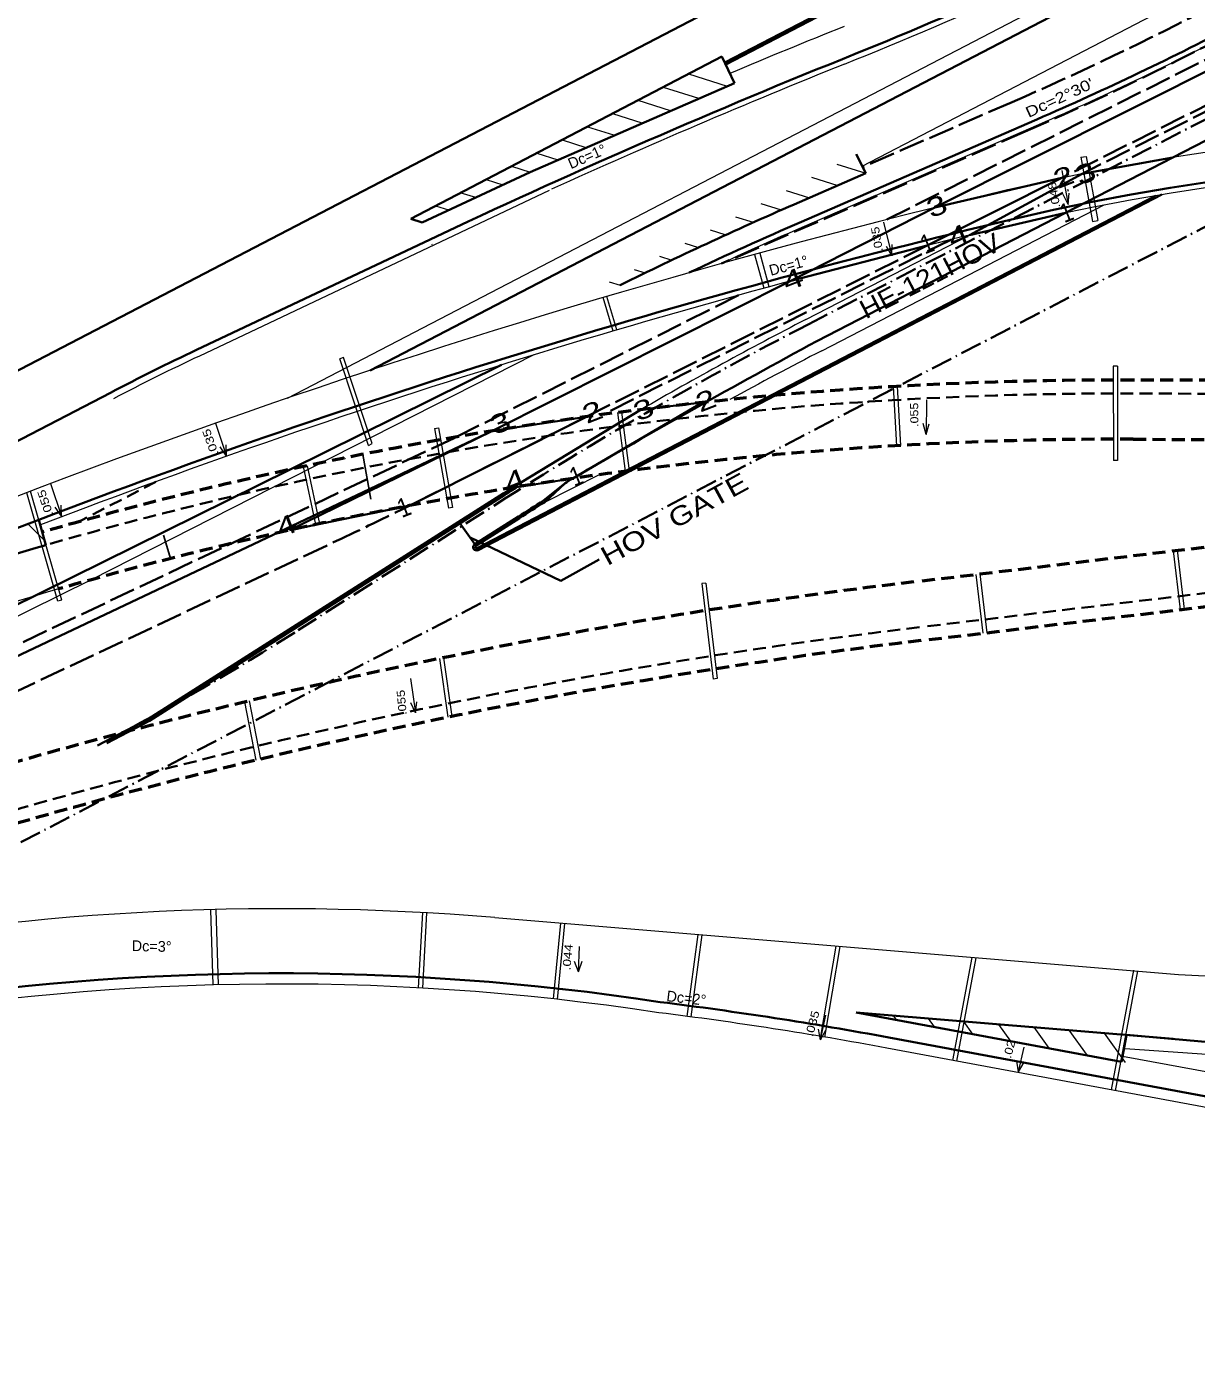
# Model space of a CAD drawing. Extents: x 2354993 to 2372084, y 6966390 to 6990057.
# Drawn here: x 2362136 to 2363006, y 6977334 to 6978319 of the extents above; entities that cross this region are included whole.
import ezdxf
from ezdxf.enums import TextEntityAlignment as Align

# ---------------------------------------------------------------- set-up
doc = ezdxf.new("R2010")
doc.units = 0
doc.header["$LTSCALE"] = 3.2
for name, pattern in [('DOT_DASHED', [7.7, 5, -1.2, 0.3, -1.2]), ('LONG_DASHED', [7.5, 6, -1.5]), ('MEDIUM_DASHED', [4.5, 3, -1.5])]:
    doc.linetypes.add(name, pattern=pattern)
for name, color, linetype, lineweight in [('12', 7, 'Continuous', 13), ('13', 7, 'Continuous', 13), ('17', 7, 'Continuous', 13), ('19', 7, 'Continuous', 13), ('2', 7, 'Continuous', 35), ('4', 7, 'Continuous', 13), ('5', 7, 'Continuous', 35), ('6', 7, 'Continuous', 35), ('61', 7, 'Continuous', 13), ('63', 7, 'Continuous', 35)]:
    doc.layers.add(name, color=color, linetype=linetype, lineweight=lineweight)

msp = doc.modelspace()

# ---------------------------------------------------------------- linework, layer by layer
at = {"layer": '12'}
for p, q in [((2362574.682, 6978093.733), (2362567.324, 6978118.67)), ((2362571.803, 6978092.884), (2362564.446, 6978117.821)), ((2362371.377, 6978073.296), (2362368.532, 6978072.348)), ((2362390.025, 6978007.891), (2362368.532, 6978072.348)), ((2362392.719, 6978009.291), (2362371.377, 6978073.296)), ((2362946.885, 6978066.796), (2362943.878, 6978066.795)), ((2362943.885, 6978066.795), (2362943.935, 6977996.56)), ((2362946.885, 6978066.796), (2362946.934, 6977996.561)), ((2362780.042, 6978051.58), (2362782.606, 6978007.655)), ((2362783.038, 6978051.756), (2362785.602, 6978007.831)), ((2362575.239, 6978032.315), (2362580.866, 6977988.676)), ((2362578.214, 6978032.698), (2362583.841, 6977989.06)), ((2362439.038, 6978020.407), (2362441.991, 6978020.93)), ((2362439.038, 6978020.407), (2362449.499, 6977961.336)), ((2362441.991, 6978020.93), (2362452.451, 6977961.859)), ((2362389.745, 6978018.211), (2362386.9, 6978017.263)), ((2362341.312, 6977992.101), (2362350.49, 6977949.069)), ((2362344.245, 6977992.726), (2362353.424, 6977949.694)), ((2362946.949, 6977996.561), (2362943.935, 6977996.56)), ((2362159.001, 6977891.989), (2362135.767, 6977972.726)), ((2362161.883, 6977892.818), (2362138.577, 6977973.802)), ((2362452.451, 6977961.859), (2362449.499, 6977961.336)), ((2362161.883, 6977892.818), (2362159.001, 6977891.989)), ((2362272.444, 6977662.559), (2362274.102, 6977606.792)), ((2362276.443, 6977662.678), (2362278.1, 6977606.896))]:
    msp.add_line(p, q, dxfattribs=at)
for points in [[(2362640.897, 6977905.496), (2362637.913, 6977905.14), (2362646.394, 6977834.183)], [(2362640.897, 6977905.496), (2362649.372, 6977834.54), (2362646.391, 6977834.183)]]:
    msp.add_lwpolyline(points, dxfattribs=at)
at = {"layer": '17'}
for p, q in [((2362919.834, 6978222.065), (2362923.771, 6978222.772)), ((2362919.834, 6978222.065), (2362928.413, 6978174.288)), ((2362923.771, 6978222.772), (2362932.35, 6978174.995)), ((2362928.413, 6978174.288), (2362932.35, 6978174.995)), ((2362677.146, 6978149.827), (2362683.958, 6978124.875)), ((2362681.005, 6978150.881), (2362687.817, 6978125.928)), ((2362546.028, 6977616.636), (2362546.795, 6977635.37)), ((2362546.028, 6977616.636), (2362543.26, 6977624.219)), ((2362546.028, 6977616.636), (2362548.839, 6977624.427)), ((2362726.084, 6977566.046), (2362730.092, 6977584.363)), ((2362726.084, 6977566.046), (2362724.675, 6977573.994)), ((2362726.084, 6977566.046), (2362730.206, 6977573.23)), ((2362873.476, 6977542.299), (2362877.484, 6977560.616)), ((2362873.476, 6977542.3), (2362872.067, 6977550.248)), ((2362873.476, 6977542.3), (2362877.598, 6977549.484))]:
    msp.add_line(p, q, dxfattribs=at)
at = {"layer": '17', "lineweight": 35}
msp.add_line((2361706.685, 6977651.285), (2362482.125, 6978018.666), dxfattribs=at)
at = {"layer": '19'}
for p, q in [((2362905.52, 6978212.363), (2362910.407, 6978187.048)), ((2362910.407, 6978187.048), (2362906.655, 6978194.465)), ((2362910.407, 6978187.048), (2362911.126, 6978195.322)), ((2362779.224, 6978148.867), (2362775.199, 6978155.884)), ((2362804.585, 6978016.032), (2362802.457, 6978024.066)), ((2362284.473, 6977999.932), (2362279.726, 6978006.753)), ((2362161.719, 6977955.18), (2362156.972, 6977962.001)), ((2362424.912, 6977809.025), (2362421.526, 6977816.614))]:
    msp.add_line(p, q, dxfattribs=at)
for points in [[(2362773.018, 6978173.891), (2362779.224, 6978148.867), (2362779.509, 6978157.168)], [(2362805.067, 6978041.81), (2362804.585, 6978016.032), (2362807.009, 6978023.976)], [(2362276.11, 6978024.32), (2362284.473, 6977999.932), (2362284.034, 6978008.226)], [(2362153.356, 6977979.568), (2362161.719, 6977955.18), (2362161.28, 6977963.474)], [(2362421.264, 6977834.548), (2362424.912, 6977809.025), (2362426.034, 6977817.254)]]:
    msp.add_lwpolyline(points, dxfattribs=at)
at = {"layer": '2'}
for p, q in [((2358006.591, 6975920.846), (2363488.891, 6978770.331)), ((2362811.106, 6978184.667), (2363604.71, 6978582.7)), ((2362988.207, 6978222.005), (2363089.737, 6978274.358)), ((2362759.919, 6978210.266), (2362752.541, 6978224.463)), ((2362975.243, 6978193.546), (2362580.871, 6977988.675)), ((2362980.038, 6978194.347), (2362692.88, 6978045.172)), ((2362723.338, 6978085.426), (2362908.292, 6978180.797)), ((2362704.108, 6978130.197), (2362482.125, 6978018.666)), ((2362692.88, 6978045.172), (2362471.439, 6977930.136)), ((2362580.871, 6977988.675), (2362470.748, 6977931.467)), ((2362226.42, 6977804.541), (2362490.493, 6977972.46)), ((2362227.174, 6977803.242), (2362491.298, 6977971.194)), ((2362468.945, 6977934.464), (2362501.492, 6977955.16)), ((2362469.73, 6977933.185), (2362502.297, 6977953.894)), ((2362457.957, 6977949.993), (2362468.945, 6977934.464)), ((2362532.928, 6977907.156), (2362465.571, 6977939.397)), ((2362532.928, 6977907.156), (2362561.479, 6977922.997))]:
    msp.add_line(p, q, dxfattribs=at)
at = {"layer": '2', "linetype": 'LONG_DASHED'}
for p, q in [((2362775.435, 6978175.726), (2363601.123, 6978589.851)), ((2363618.55, 6978565.019), (2362905.562, 6978206.794)), ((2363084.717, 6978292.33), (2362920.65, 6978209.898)), ((2362868.725, 6978263.158), (2362757.536, 6978214.854)), ((2362878.281, 6978241.142), (2362652.39, 6978143.01)), ((2362822.936, 6978160.805), (2362564.328, 6978030.873)), ((2362805.354, 6978156.448), (2362420.606, 6977963.184)), ((2362665.112, 6978119.556), (2362455.357, 6978014.169)), ((2361699.088, 6977656.554), (2362455.357, 6978014.169)), ((2361711.836, 6977629.398), (2362366.21, 6977936.92))]:
    msp.add_line(p, q, dxfattribs=at)
at = {"layer": '2', "linetype": 'MEDIUM_DASHED'}
msp.add_line((2362231.704, 6977980.832), (2362174.616, 6977951.163), dxfattribs=at)
at = {"layer": '2', "linetype": 'LONG_DASHED'}
for centre, radius, start, end in [((2361957.93, 6980359.697), 2285.831, 293.48147, 297.64944), ((2361957.927, 6980359.696), 2309.831, 293.48137, 297.6495), ((2361144.348, 6980536.913), 2872.789, 295.17109, 296.37586)]:
    msp.add_arc(centre, radius, start, end, dxfattribs=at)
at = {"layer": '2'}
for centre, radius, start, end in [((2365652.69, 6972668.039), 6158.667, 118.40149, 120.33806), ((2364029.86, 6975551.655), 2850.789, 121.46196, 121.59891), ((2364029.86, 6975551.655), 2868.789, 122.30227, 122.45191), ((2364029.86, 6975551.655), 2867.289, 122.23233, 122.45191), ((2364029.86, 6975551.655), 2848.289, 122.00852, 122.45191), ((2364029.86, 6975551.655), 2846.789, 122.01179, 122.45191), ((2362470.287, 6977932.355), 2.5, 122.45143, 297.45154), ((2362470.287, 6977932.355), 1, 122.45143, 297.45154)]:
    msp.add_arc(centre, radius, start, end, dxfattribs=at)
at = {"layer": '4'}
msp.add_line((2362757.154, 6978215.587), (2363268.695, 6978481.438), dxfattribs=at)
at = {"layer": '4', "lineweight": 25}
for p, q in [((2362385.833, 6978001.212), (2362391.796, 6977967.815)), ((2362242.862, 6977923.152), (2362237.538, 6977941.259))]:
    msp.add_line(p, q, dxfattribs=at)
at = {"layer": '4', "lineweight": 35}
for p in [(2362520.138, 6977966.916), (2362520.795, 6977965.558)]:
    msp.add_line(p, (2362536.133, 6977979.777), dxfattribs=at)
at = {"layer": '5'}
for p, q in [((2362087.371, 6978041.876), (2363419.143, 6978734.078)), ((2362654.988, 6978292.473), (2363507.292, 6978735.395)), ((2362655.626, 6978291.114), (2363508.018, 6978734.082)), ((2362391.142, 6978063.692), (2363583.984, 6978683.611)), ((2362652.848, 6978297.032), (2362421.419, 6978176.314)), ((2362652.848, 6978297.032), (2362662.138, 6978277.243)), ((2362742.392, 6978295.091), (2362751.833, 6978298.893)), ((2362765.497, 6978197.425), (2362886.96, 6978250.192)), ((2362759.919, 6978210.266), (2362706.512, 6978187.064)), ((2362765.497, 6978197.425), (2362712.091, 6978174.224)), ((2362421.419, 6978176.314), (2362429.768, 6978173.689)), ((2362435.758, 6978161.035), (2362262.045, 6978078.872)), ((2361730.202, 6977803.996), (2362197.968, 6978047.082)), ((2362144.684, 6977952.584), (2362150.078, 6977933.84)), ((2362226.42, 6977804.541), (2362188.485, 6977784.834)), ((2362227.178, 6977803.244), (2362195.267, 6977786.667)), ((2362752.746, 6977586.338), (2362988.499, 6977566.726)), ((2363437.708, 6977444.706), (2362776.995, 6977567.714)), ((2362949.929, 6977549.759), (2362953.59, 6977569.421)), ((2363056.715, 6977560.454), (2362953.628, 6977569.627))]:
    msp.add_line(p, q, dxfattribs=at)
at = {"layer": '5', "lineweight": 13}
for p, q in [((2362329.78, 6978043.07), (2363248.405, 6978520.479)), ((2362627.951, 6978284.047), (2362656.76, 6978274.985)), ((2362609.144, 6978274.236), (2362635.439, 6978265.969)), ((2362590.336, 6978264.425), (2362614.259, 6978256.904)), ((2362571.528, 6978254.614), (2362593.203, 6978247.8)), ((2362767.091, 6978193.757), (2362888.554, 6978246.524)), ((2362552.719, 6978244.803), (2362572.28, 6978238.654)), ((2362533.911, 6978234.992), (2362551.488, 6978229.467)), ((2362515.102, 6978225.182), (2362530.824, 6978220.239)), ((2362738.3, 6978217.063), (2362759.919, 6978210.266)), ((2362496.294, 6978215.371), (2362510.289, 6978210.971)), ((2362719.45, 6978207.266), (2362738.922, 6978201.144)), ((2362524.395, 6978197.427), (2362264.183, 6978074.352)), ((2362477.487, 6978205.559), (2362489.88, 6978201.664)), ((2362700.597, 6978197.468), (2362717.922, 6978192.021)), ((2362458.678, 6978195.749), (2362469.594, 6978192.317)), ((2362681.747, 6978187.672), (2362696.925, 6978182.899)), ((2362767.091, 6978193.756), (2362713.852, 6978170.627)), ((2362439.869, 6978185.939), (2362449.429, 6978182.933)), ((2362662.895, 6978177.874), (2362675.926, 6978173.777)), ((2362727.004, 6978078.316), (2362937.068, 6978186.635)), ((2362644.044, 6978168.078), (2362654.929, 6978164.655)), ((2362435.377, 6978160.855), (2362435.764, 6978161.038)), ((2362437.088, 6978157.239), (2362437.474, 6978157.422)), ((2362625.192, 6978158.28), (2362635.464, 6978155.051)), ((2362715.089, 6978101.424), (2362836.859, 6978164.214)), ((2362606.34, 6978148.483), (2362615.458, 6978145.615)), ((2362587.489, 6978138.686), (2362595.692, 6978136.108)), ((2362568.958, 6978129.604), (2362577.161, 6978127.026)), ((2362512.875, 6978075.151), (2362183.72, 6977908.026)), ((2362562.03, 6977986.161), (2362520.795, 6977965.558)), ((2362136.625, 6977949.49), (2362149.095, 6977937.256)), ((2362183.72, 6977908.026), (2361804.561, 6977720.528)), ((2362483.973, 6977656.862), (2362992.478, 6977614.561)), ((2362782.547, 6977580.921), (2362780.307, 6977584.045)), ((2362810.95, 6977575.633), (2362806.479, 6977581.868)), ((2362839.354, 6977570.345), (2362832.652, 6977579.691)), ((2362867.758, 6977565.057), (2362858.825, 6977577.513)), ((2362896.161, 6977559.769), (2362884.997, 6977575.336)), ((2362924.565, 6977554.481), (2362911.17, 6977573.159)), ((2362952.969, 6977549.193), (2362937.343, 6977570.982)), ((2363436.244, 6977436.841), (2362775.531, 6977559.85)), ((2362952.814, 6977559.66), (2363056.326, 6977552.462)), ((2363441.003, 6977462.402), (2362950.662, 6977553.691))]:
    msp.add_line(p, q, dxfattribs=at)
at = {"layer": '5', "linetype": 'MEDIUM_DASHED', "lineweight": 53}
for p, q in [((2363881.241, 6978053.379), (2362958.761, 6978056.492)), ((2362958.612, 6978012.492), (2363716.295, 6978009.935)), ((2362801.702, 6977907.216), (2363080.587, 6977940.529)), ((2362806.918, 6977863.526), (2363091.58, 6977897.529))]:
    msp.add_line(p, q, dxfattribs=at)
at = {"layer": '5', "linetype": 'MEDIUM_DASHED'}
for p, q in [((2363836.954, 6978043.529), (2362958.726, 6978046.492)), ((2362805.732, 6977873.455), (2363090.394, 6977907.458))]:
    msp.add_line(p, q, dxfattribs=at)
at = {"layer": '5'}
for points in [[(2362662.138, 6978277.243), (2362510.289, 6978210.971), (2362429.768, 6978173.689)], [(2362488.793, 6978067.704), (2362331.734, 6977990.029), (2361705.614, 6977680.376)], [(2362949.929, 6977549.759), (2362839.354, 6977570.345), (2362752.746, 6977586.338)]]:
    msp.add_lwpolyline(points, dxfattribs=at)
for centre, radius, start, end in [((2361676.37, 6980969.25), 2878.789, 291.93666, 297.46082), ((2361968.189, 6980365.073), 2305.831, 293.48164, 297.64942), ((2364877.625, 6972993.336), 5715.578, 111.93666, 115.2919), ((2363244.672, 6976597.082), 1623.014, 38.12295, 103.3303), ((2363855.57, 6975542.087), 2883.789, 113.48158, 116.31519), ((2364188.171, 6972614.757), 5715.613, 103.3303, 110.94842), ((2363855.57, 6975542.087), 2869.789, 113.48158, 115.31325), ((2363078.527, 6976352.647), 1909.58, 115.31354, 117.45987), ((2364188.16, 6972614.79), 5715.578, 110.94799, 113.39373), ((2362948.983, 6975157.719), 2888.789, 106.05464, 110.92598), ((2362324.651, 6975741.618), 1873.859, 81.33444, 116.95937), ((2362255.214, 6974765.083), 2850.789, 79.45368, 82.91209)]:
    msp.add_arc(centre, radius, start, end, dxfattribs=at)
at = {"layer": '5', "lineweight": 13}
for centre, radius, start, end in [((2361676.37, 6980969.25), 2882.789, 291.73437, 297.46082), ((2364877.625, 6972993.336), 5737.578, 111.83502, 112.75114), ((2361968.189, 6980365.073), 2309.831, 293.48164, 297.64942), ((2364877.625, 6972993.336), 5711.578, 111.93666, 114.31325), ((2363244.672, 6976597.082), 1645.014, 38.12295, 103.3303), ((2363244.672, 6976597.082), 1619.014, 38.12295, 103.3303), ((2364188.171, 6972614.757), 5737.613, 103.3303, 115.98006), ((2364188.171, 6972614.757), 5711.613, 103.3303, 110.94842), ((2363858.925, 6975534.821), 2873.789, 113.48158, 114.8312), ((2364029.86, 6975551.655), 2868.789, 117.27758, 120.0623), ((2363078.527, 6976352.647), 1904.58, 115.31354, 117.45987), ((2364029.86, 6975551.655), 2842.789, 117.27758, 118.83624), ((2363097.562, 6979328.645), 1717.302, 266.49182, 308.27248), ((2362948.983, 6975157.719), 2854.789, 106.05463, 117.46086), ((2362324.651, 6975741.618), 1921.859, 85.24473, 116.95937), ((2362324.651, 6975741.618), 1865.859, 81.33444, 119.61246), ((2362255.214, 6974765.083), 2842.789, 79.45368, 82.91209)]:
    msp.add_arc(centre, radius, start, end, dxfattribs=at)
at = {"layer": '5', "linetype": 'MEDIUM_DASHED', "lineweight": 53}
for centre, radius, start, end in [((2362948.983, 6975157.719), 2898.789, 89.80675, 106.05463), ((2362948.983, 6975157.719), 2854.789, 89.80675, 106.05463), ((2363306.843, 6973626.915), 4310, 96.81172, 111.72863), ((2363306.843, 6973626.915), 4266, 96.81171, 111.74968)]:
    msp.add_arc(centre, radius, start, end, dxfattribs=at)
at = {"layer": '5', "linetype": 'MEDIUM_DASHED'}
for centre, radius, start, end in [((2362948.983, 6975157.719), 2888.789, 89.80675, 106.05464), ((2363306.843, 6973626.915), 4276, 96.81172, 116.96246)]:
    msp.add_arc(centre, radius, start, end, dxfattribs=at)
at = {"layer": '6', "linetype": 'DOT_DASHED'}
for p, q in [((2360272.717, 6976747.357), (2363548.144, 6978448.903)), ((2360272.718, 6976747.358), (2363548.137, 6978448.9)), ((2360272.718, 6976747.358), (2363548.137, 6978448.9)), ((2362716.922, 6978097.869), (2363083.321, 6978286.801)), ((2362337.537, 6977870.457), (2362492.639, 6977969.084))]:
    msp.add_line(p, q, dxfattribs=at)
at = {"layer": '6', "lineweight": 13}
msp.add_line((2362390.025, 6978007.891), (2362392.719, 6978009.291), dxfattribs=at)
at = {"layer": '6', "linetype": 'DOT_DASHED'}
for centre, radius, start, end in [((2364029.86, 6975551.655), 2864.789, 117.27758, 122.45191), ((2361312.723, 6979482.076), 1909.859, 297.45108, 302.45191)]:
    msp.add_arc(centre, radius, start, end, dxfattribs=at)
at = {"layer": '61'}
for p, q in [((2362993.869, 6977885.857), (2362988.65, 6977929.547)), ((2362996.848, 6977886.213), (2362991.629, 6977929.903)), ((2362841.545, 6977911.976), (2362846.764, 6977868.285)), ((2362844.525, 6977912.332), (2362849.744, 6977868.641)), ((2362442.748, 6977849.407), (2362448.913, 6977805.756)), ((2362445.692, 6977850.009), (2362451.857, 6977806.359)), ((2362306.338, 6977773.932), (2362297.932, 6977817.166)), ((2362309.808, 6977774.767), (2362301.402, 6977818)), ((2362427.265, 6977604.653), (2362430.344, 6977660.569)), ((2362430.26, 6977604.486), (2362433.34, 6977660.401)), ((2362527.512, 6977596.417), (2362532.933, 6977652.789)), ((2362530.494, 6977596.088), (2362535.923, 6977652.54)), ((2362626.951, 6977583.464), (2362635.04, 6977644.295)), ((2362629.925, 6977583.068), (2362638.033, 6977644.046)), ((2362726.321, 6977568.566), (2362737.685, 6977635.756)), ((2362729.279, 6977568.066), (2362740.685, 6977635.507)), ((2362824.628, 6977550.709), (2362838.894, 6977627.337)), ((2362827.577, 6977550.16), (2362841.899, 6977627.087)), ((2362942.551, 6977528.755), (2362959.144, 6977617.883)), ((2362945.5, 6977528.205), (2362962.094, 6977617.334))]:
    msp.add_line(p, q, dxfattribs=at)
at = {"layer": '63'}
for points in [[(2362920.65, 6978209.898), (2362988.208, 6978222.005), (2362908.292, 6978180.797), (2362836.859, 6978164.214)], [(2362811.106, 6978184.667), (2362905.562, 6978206.794), (2362805.354, 6978156.448), (2362704.108, 6978130.197)], [(2362638.461, 6978039.828), (2362541.941, 6977983.34), (2362496.82, 6977976.472), (2362592.765, 6978034.538)]]:
    msp.add_lwpolyline(points, close=True, dxfattribs=at)
for points in [[(2362331.305, 6977944.885), (2362482.125, 6978018.666), (2362552.11, 6978029.211)], [(2362552.11, 6978029.211), (2362420.606, 6977963.184), (2362331.305, 6977944.885)]]:
    msp.add_lwpolyline(points, dxfattribs=at)

# ---------------------------------------------------------------- texts
at = {"layer": '13'}
for s, rotation, width, p in [('HE-121HOV', 27.223, 1.1, (2362759.896, 6978101.552)), ('HOV GATE', 28.633, 1.25, (2362567.656, 6977918.108))]:
    msp.add_text(s, height=14, rotation=rotation, dxfattribs=dict(at, width=width)).set_placement(p)
at = {"layer": '17'}
for s, height, rotation, width, p in [("Dc=2°30'", 7.999, 24.802, 1.25, (2362880.913, 6978251.29)), ('.044', 6, 84.81, 1.25, (2362540.087, 6977617.514)), ('.035', 6, 74.81, 1.25, (2362720.383, 6977567.945)), ('.02', 6, 74.81, 1.2, (2362867.687, 6977551.811))]:
    msp.add_text(s, height=height, rotation=rotation, dxfattribs=dict(at, width=width)).set_placement(p)
for s, height, rotation, p in [('Dc=1°', 8, 23.248, (2362540.482, 6978213.224)), ('Dc=1°', 7.999, 15.237, (2362689.189, 6978133.937)), ('Dc=3°', 8, 358.484, (2362213.825, 6977632.036)), ('Dc=2°', 8, 353.484, (2362611.24, 6977594.771))]:
    msp.add_text(s, height=height, rotation=rotation, dxfattribs=at).set_placement(p)
at = {"layer": '19'}
for s, height, rotation, width, p in [('.048', 5.999, 100.687, 1.25, (2362904.55, 6978184.965)), ('.035', 6, 99.534, 1.2, (2362772.594, 6978152.386)), ('.055', 6, 90.548, 1.15, (2362798.93, 6978021.713)), ('.035', 6, 109.909, 1.3, (2362278.641, 6978001.811)), ('.055', 5.999, 109.007, 1.3, (2362155.721, 6977956.452)), ('.055', 6, 95.052, 1.2, (2362418.423, 6977807.745))]:
    msp.add_text(s, height=height, rotation=rotation, dxfattribs=dict(at, width=width)).set_placement(p)
at = {"layer": '63'}
for s, width, p in [('3', 1.4, (2362925.679, 6978203.606)), ('2', 1.4, (2362909.422, 6978201.03)), ('3', 1.4, (2362815.101, 6978179.293)), ('1', 0.85, (2362911.514, 6978174.623)), ('4', 1.45, (2362831.047, 6978157.403)), ('1', 0.85, (2362807.857, 6978151.437)), ('4', 1.45, (2362708.075, 6978124.878)), ('2', 1.4, (2362643.335, 6978034.822)), ('2', 1.4, (2362559.023, 6978026.309)), ('3', 1.4, (2362597.009, 6978028.241)), ('3', 1.4, (2362490.455, 6978018.097)), ('4', 1.45, (2362501.217, 6977975.586)), ('1', 0.85, (2362546.95, 6977978.648)), ('1', 0.85, (2362418.828, 6977955.462)), ('4', 1.45, (2362331.279, 6977941.784))]:
    msp.add_text(s, height=14, rotation=21.221, dxfattribs=dict(at, width=width)).set_placement(p, align=Align.CENTER)

doc.saveas('drawing.dxf')
